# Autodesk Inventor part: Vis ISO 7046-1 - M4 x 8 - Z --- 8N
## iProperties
Created: 2011-01
Part Number: Vis ISO 7046-1 - M4 x 8 - Z --- 8N
Document SubType Name: Modeling
Designer: eric
Density: 1 g/cm^3
Mass: 0.149531 g
Surface Area: 2.33924 cm^2
Volume: 0.149531 cm^3
Author: eric
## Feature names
1. Base1
